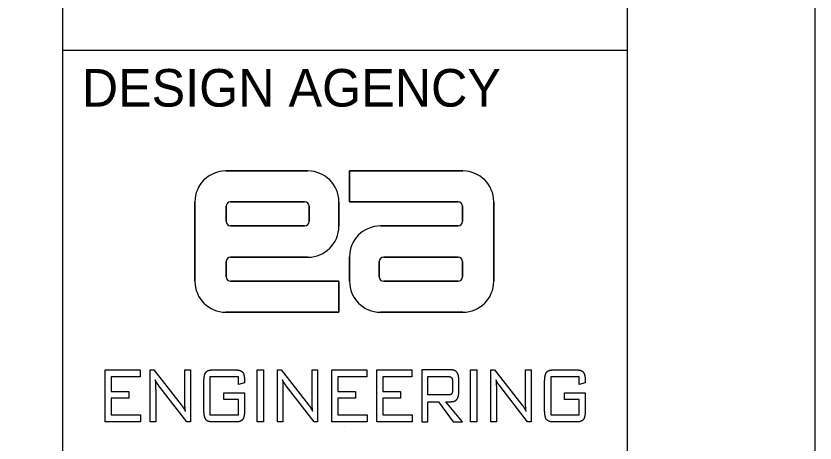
# Model space of a CAD drawing. Extents: x 0 to 34, y 0 to 22.
# Drawn here: x 31.875 to 34, y 3.455 to 4.591 of the extents above; entities that cross this region are included whole.
import ezdxf

# ---------------------------------------------------------------- set-up
doc = ezdxf.new("R2010")
doc.units = 0
for name, color, linetype in [('SH_Border', 7, 'Continuous'), ('SH_Cut_Line', 7, 'Continuous'), ('SH_Data', 7, 'Continuous'), ('SH_Text', 7, 'Continuous')]:
    doc.layers.add(name, color=color, linetype=linetype)

msp = doc.modelspace()

# ---------------------------------------------------------------- linework, layer by layer
at = {"layer": 'SH_Border'}
for p, q in [((32, 0.5), (32, 21.5)), ((32, 4.5), (33.5, 4.5))]:
    msp.add_line(p, q, dxfattribs=at)
msp.add_lwpolyline([(1.5, 21.5), (33.5, 21.5), (33.5, 0.5), (1.5, 0.5)], close=True, dxfattribs=at)
at = {"layer": 'SH_Cut_Line'}
msp.add_lwpolyline([(0, 0), (34, 0), (34, 22), (0, 22)], close=True, dxfattribs=at)
at = {"layer": 'SH_Data'}
msp.add_line((32.75, 3.5), (32.75, 3.5), dxfattribs=at)
at = {"layer": 'SH_Text'}
for p, q in [((32.6515, 4.1788), (32.433, 4.1788)), ((32.433, 4.1788), (32.6515, 4.1788)), ((32.762, 4.1788), (33.0635, 4.1788)), ((32.762, 4.0967), (32.762, 4.1788)), ((32.351, 4.0967), (32.351, 3.8852)), ((32.351, 3.8852), (32.351, 4.0967)), ((32.434, 4.0444), (32.434, 4.0849)), ((32.434, 4.0849), (32.434, 4.0444)), ((32.4459, 4.0967), (32.6426, 4.0967)), ((32.6426, 4.0967), (32.4459, 4.0967)), ((32.6545, 4.0849), (32.6545, 4.0444)), ((32.6545, 4.0444), (32.6545, 4.0849)), ((32.7336, 4.0315), (32.7336, 4.0967)), ((32.7336, 4.0967), (32.7336, 4.0315)), ((33.0507, 4.0967), (32.762, 4.0967)), ((33.0626, 4.0849), (33.0626, 4.0444)), ((33.0626, 4.0444), (33.0626, 4.0849)), ((33.1456, 3.8852), (33.1456, 4.0967)), ((33.1456, 4.0967), (33.1456, 3.8852)), ((32.6426, 4.0325), (32.4459, 4.0325)), ((32.4459, 4.0325), (32.6426, 4.0325)), ((33.0507, 4.0325), (32.8441, 4.0325)), ((32.8441, 4.0325), (33.0507, 4.0325)), ((32.434, 3.8971), (32.434, 3.9376)), ((32.434, 3.9376), (32.434, 3.8971)), ((32.4459, 3.9494), (32.6515, 3.9494)), ((32.6515, 3.9494), (32.4459, 3.9494)), ((32.762, 3.9504), (32.762, 3.8852)), ((32.762, 3.8852), (32.762, 3.9504)), ((32.8411, 3.8971), (32.8411, 3.9376)), ((32.8411, 3.9376), (32.8411, 3.8971)), ((32.853, 3.9494), (33.0507, 3.9494)), ((33.0507, 3.9494), (32.853, 3.9494)), ((33.0626, 3.9376), (33.0626, 3.8971)), ((33.0626, 3.8971), (33.0626, 3.9376)), ((32.4459, 3.8852), (32.7336, 3.8852)), ((32.7336, 3.8852), (32.7336, 3.8031)), ((33.0507, 3.8852), (32.853, 3.8852)), ((32.853, 3.8852), (33.0507, 3.8852)), ((32.7336, 3.8031), (32.433, 3.8031)), ((32.8441, 3.8031), (33.0635, 3.8031)), ((33.0635, 3.8031), (32.8441, 3.8031)), ((32.3975, 3.6495), (32.4602, 3.6495)), ((33.3037, 3.6495), (33.3663, 3.6495)), ((32.3748, 3.5439), (32.3748, 3.6168)), ((33.0361, 3.6173), (33.0361, 3.5971)), ((33.0526, 3.5917), (33.0526, 3.6227)), ((33.2809, 3.5439), (33.2809, 3.6168)), ((32.4602, 3.5111), (32.3975, 3.5111)), ((33.3663, 3.5111), (33.3037, 3.5111))]:
    msp.add_line(p, q, dxfattribs=at)
for points in [[(33.0635, 4.1788), (32.762, 4.1788), (32.762, 4.0967), (33.0507, 4.0967)], [(32.433, 3.8031), (32.7336, 3.8031), (32.7336, 3.8852), (32.4459, 3.8852)], [(32.2465, 3.5927), (32.2465, 3.5111), (32.2317, 3.5111), (32.2317, 3.6495), (32.2419, 3.6495), (32.3144, 3.5569)], [(32.3239, 3.5736), (32.3239, 3.6495), (32.3387, 3.6495), (32.3387, 3.5111), (32.3297, 3.5111), (32.2553, 3.6074)], [(32.5851, 3.5927), (32.5851, 3.5111), (32.5703, 3.5111), (32.5703, 3.6495), (32.5804, 3.6495), (32.6529, 3.5569)], [(32.6625, 3.5736), (32.6625, 3.6495), (32.6773, 3.6495), (32.6773, 3.5111), (32.6682, 3.5111), (32.5938, 3.6074)], [(33.032, 3.6495), (32.954, 3.6495), (32.954, 3.5111), (32.9702, 3.5111), (32.9702, 3.565), (32.9987, 3.565), (33.0381, 3.5111), (33.0621, 3.5111), (33.0178, 3.565), (33.032, 3.565)], [(33.1527, 3.5927), (33.1527, 3.5111), (33.1379, 3.5111), (33.1379, 3.6495), (33.148, 3.6495), (33.2205, 3.5569)], [(33.2301, 3.5736), (33.2301, 3.6495), (33.2449, 3.6495), (33.2449, 3.5111), (33.2358, 3.5111), (33.1614, 3.6074)], [(32.483, 3.6183), (32.483, 3.6149), (32.4668, 3.6103), (32.4668, 3.6307), (32.3909, 3.6307), (32.3909, 3.5304), (32.4668, 3.5304), (32.4668, 3.571), (32.4276, 3.571), (32.4276, 3.5886), (32.483, 3.5886), (32.483, 3.5439)], [(33.0257, 3.5829), (32.9702, 3.5829), (32.9702, 3.6316), (33.0257, 3.6316)], [(33.3891, 3.6183), (33.3891, 3.6149), (33.3729, 3.6103), (33.3729, 3.6307), (33.2971, 3.6307), (33.2971, 3.5304), (33.3729, 3.5304), (33.3729, 3.571), (33.3338, 3.571), (33.3338, 3.5886), (33.3891, 3.5886), (33.3891, 3.5439)]]:
    msp.add_lwpolyline(points, dxfattribs=at)
for points in [[(32.1121, 3.5111), (32.1121, 3.6495), (32.2053, 3.6495), (32.2053, 3.631), (32.1283, 3.631), (32.1283, 3.5925), (32.1754, 3.5925), (32.1754, 3.5742), (32.1283, 3.5742), (32.1283, 3.5301), (32.2061, 3.5301), (32.2061, 3.5111)], [(32.5166, 3.5111), (32.5166, 3.6495), (32.5329, 3.6495), (32.5329, 3.5111)], [(32.7147, 3.5111), (32.7147, 3.6495), (32.8079, 3.6495), (32.8079, 3.631), (32.7309, 3.631), (32.7309, 3.5925), (32.778, 3.5925), (32.778, 3.5742), (32.7309, 3.5742), (32.7309, 3.5301), (32.8087, 3.5301), (32.8087, 3.5111)], [(32.8343, 3.5111), (32.8343, 3.6495), (32.9276, 3.6495), (32.9276, 3.631), (32.8506, 3.631), (32.8506, 3.5925), (32.8977, 3.5925), (32.8977, 3.5742), (32.8506, 3.5742), (32.8506, 3.5301), (32.9283, 3.5301), (32.9283, 3.5111)], [(33.0842, 3.5111), (33.0842, 3.6495), (33.1005, 3.6495), (33.1005, 3.5111)]]:
    msp.add_lwpolyline(points, close=True, dxfattribs=at)
for centre, radius, start, end in [((32.433, 4.0967), 0.0821, 90, 180), ((32.433, 4.0967), 0.0821, 90, 180), ((32.6515, 4.0967), 0.0821, 0, 90), ((32.6515, 4.0967), 0.0821, 0, 90), ((33.0635, 4.0967), 0.0821, 0, 90), ((33.0635, 4.0967), 0.0821, 0, 90), ((32.4459, 4.0849), 0.0119, 90, 180), ((32.4459, 4.0849), 0.0119, 90, 180), ((32.6426, 4.0849), 0.0119, 0, 90), ((32.6426, 4.0849), 0.0119, 0, 90), ((33.0507, 4.0849), 0.0119, 0, 90), ((33.0507, 4.0849), 0.0119, 0, 90), ((32.4459, 4.0444), 0.0119, 180, 270), ((32.4459, 4.0444), 0.0119, 180, 270), ((32.6426, 4.0444), 0.0119, 270, 0), ((32.6426, 4.0444), 0.0119, 270, 0), ((33.0507, 4.0444), 0.0119, 270, 0), ((33.0507, 4.0444), 0.0119, 270, 0), ((32.6515, 4.0315), 0.0821, 270, 360), ((32.6515, 4.0315), 0.0821, 270, 360), ((32.8441, 3.9504), 0.0821, 90, 180), ((32.8441, 3.9504), 0.0821, 90, 180), ((32.4459, 3.9376), 0.0119, 90, 180), ((32.4459, 3.9376), 0.0119, 90, 180), ((32.853, 3.9376), 0.0119, 90, 180), ((32.853, 3.9376), 0.0119, 90, 180), ((33.0507, 3.9376), 0.0119, 0, 90), ((33.0507, 3.9376), 0.0119, 0, 90), ((32.4459, 3.8971), 0.0119, 180, 270), ((32.4459, 3.8971), 0.0119, 180, 270), ((32.853, 3.8971), 0.0119, 180, 270), ((32.853, 3.8971), 0.0119, 180, 270), ((33.0507, 3.8971), 0.0119, 270, 0), ((33.0507, 3.8971), 0.0119, 270, 0), ((32.433, 3.8852), 0.0821, 180, 270), ((32.433, 3.8852), 0.0821, 180, 270), ((32.8441, 3.8852), 0.0821, 180, 270), ((32.8441, 3.8852), 0.0821, 180, 270), ((33.0635, 3.8852), 0.0821, 270, 360), ((33.0635, 3.8852), 0.0821, 270, 360)]:
    msp.add_arc(centre, radius, start, end, dxfattribs=at)
for points in [[(32.3748, 3.6168), (32.3748, 3.6356), (32.3795, 3.6426)], [(32.3795, 3.6426), (32.3842, 3.6495), (32.3975, 3.6495)], [(32.4602, 3.6495), (32.4732, 3.6495), (32.4781, 3.6428)], [(32.4781, 3.6428), (32.483, 3.636), (32.483, 3.6183)], [(33.0477, 3.6432), (33.0429, 3.6495), (33.032, 3.6495)], [(33.0526, 3.6227), (33.0526, 3.6368), (33.0477, 3.6432)], [(33.2809, 3.6168), (33.2809, 3.6356), (33.2857, 3.6426)], [(33.2857, 3.6426), (33.2904, 3.6495), (33.3037, 3.6495)], [(33.3663, 3.6495), (33.3794, 3.6495), (33.3842, 3.6428)], [(33.3842, 3.6428), (33.3891, 3.636), (33.3891, 3.6183)], [(32.2536, 3.6094), (32.2481, 3.6165), (32.2454, 3.6229)], [(32.2454, 3.6229), (32.246, 3.6166), (32.2463, 3.6095)], [(32.5921, 3.6094), (32.5866, 3.6165), (32.584, 3.6229)], [(32.584, 3.6229), (32.5845, 3.6166), (32.5848, 3.6095)], [(33.0257, 3.6316), (33.0316, 3.6316), (33.0339, 3.6284)], [(33.0339, 3.6284), (33.0361, 3.6252), (33.0361, 3.6173)], [(33.1597, 3.6094), (33.1542, 3.6165), (33.1516, 3.6229)], [(33.1516, 3.6229), (33.1521, 3.6166), (33.1524, 3.6095)], [(32.2463, 3.6095), (32.2465, 3.6024), (32.2465, 3.5927)], [(32.2553, 3.6074), (32.2547, 3.608), (32.2536, 3.6094)], [(32.5848, 3.6095), (32.5851, 3.6024), (32.5851, 3.5927)], [(32.5938, 3.6074), (32.5932, 3.608), (32.5921, 3.6094)], [(33.0361, 3.5971), (33.0361, 3.5892), (33.0339, 3.5861)], [(33.0477, 3.5714), (33.0526, 3.5777), (33.0526, 3.5917)], [(33.1524, 3.6095), (33.1527, 3.6024), (33.1527, 3.5927)], [(33.1614, 3.6074), (33.1608, 3.608), (33.1597, 3.6094)], [(32.3243, 3.5535), (32.3239, 3.5607), (32.3239, 3.5736)], [(32.6628, 3.5535), (32.6625, 3.5607), (32.6625, 3.5736)], [(33.0339, 3.5861), (33.0317, 3.5829), (33.0257, 3.5829)], [(33.032, 3.565), (33.0429, 3.565), (33.0477, 3.5714)], [(33.2304, 3.5535), (33.2301, 3.5607), (33.2301, 3.5736)], [(32.3144, 3.5569), (32.3169, 3.5538), (32.3197, 3.5493)], [(32.3197, 3.5493), (32.3225, 3.5449), (32.3254, 3.5395)], [(32.3254, 3.5395), (32.3247, 3.5462), (32.3243, 3.5535)], [(32.6529, 3.5569), (32.6554, 3.5538), (32.6582, 3.5493)], [(32.6582, 3.5493), (32.661, 3.5449), (32.6639, 3.5395)], [(32.6639, 3.5395), (32.6632, 3.5462), (32.6628, 3.5535)], [(33.2205, 3.5569), (33.223, 3.5538), (33.2258, 3.5493)], [(33.2258, 3.5493), (33.2286, 3.5449), (33.2315, 3.5395)], [(33.2315, 3.5395), (33.2308, 3.5462), (33.2304, 3.5535)], [(32.3795, 3.5181), (32.3748, 3.525), (32.3748, 3.5439)], [(32.483, 3.5439), (32.483, 3.5249), (32.4782, 3.518)], [(33.2857, 3.5181), (33.2809, 3.525), (33.2809, 3.5439)], [(33.3891, 3.5439), (33.3891, 3.5249), (33.3843, 3.518)], [(32.3975, 3.5111), (32.3842, 3.5111), (32.3795, 3.5181)], [(32.4782, 3.518), (32.4734, 3.5111), (32.4602, 3.5111)], [(33.3037, 3.5111), (33.2904, 3.5111), (33.2857, 3.5181)], [(33.3843, 3.518), (33.3795, 3.5111), (33.3663, 3.5111)]]:
    msp.add_open_spline(points, degree=2, dxfattribs=at)

# ---------------------------------------------------------------- texts
at = {"layer": 'SH_Data'}
msp.add_text('DESIGN AGENCY', height=0.1, dxfattribs=at).set_placement((32.05, 4.35))

doc.saveas('drawing.dxf')
